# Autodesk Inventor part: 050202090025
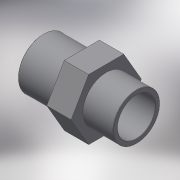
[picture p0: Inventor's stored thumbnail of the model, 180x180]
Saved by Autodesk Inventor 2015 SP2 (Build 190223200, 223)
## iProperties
Created: 2017-10
Part Number: 050202090025
Material: Generic
Description: PLASSON REDUCER THR-CEM PVC 90(75)2.1/2"F
Document SubType Name: Modeling
Designer: KIM
Density: 1 g/cm^3
Appearance: Default
Author: KIM
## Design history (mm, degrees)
derived "050202.ipt"
feature "Solid1::050202.ipt"
tag "TaggingFeature1"
body "Solid1"
other parameters: "d0" = 94, "d1" = 75, "d2" = 95, "d3" = 72.226, "d4" = 67.5, "d6" = 29, "d8" = 86.25, "d13" = 0, "d14" = 0.75, "d17" = 51, "d18" = 34.8, "d_" = 75, "G_" = 72.226, "C_" = 95, "L_" = 51, "lt_" = 29, "H_" = 94
